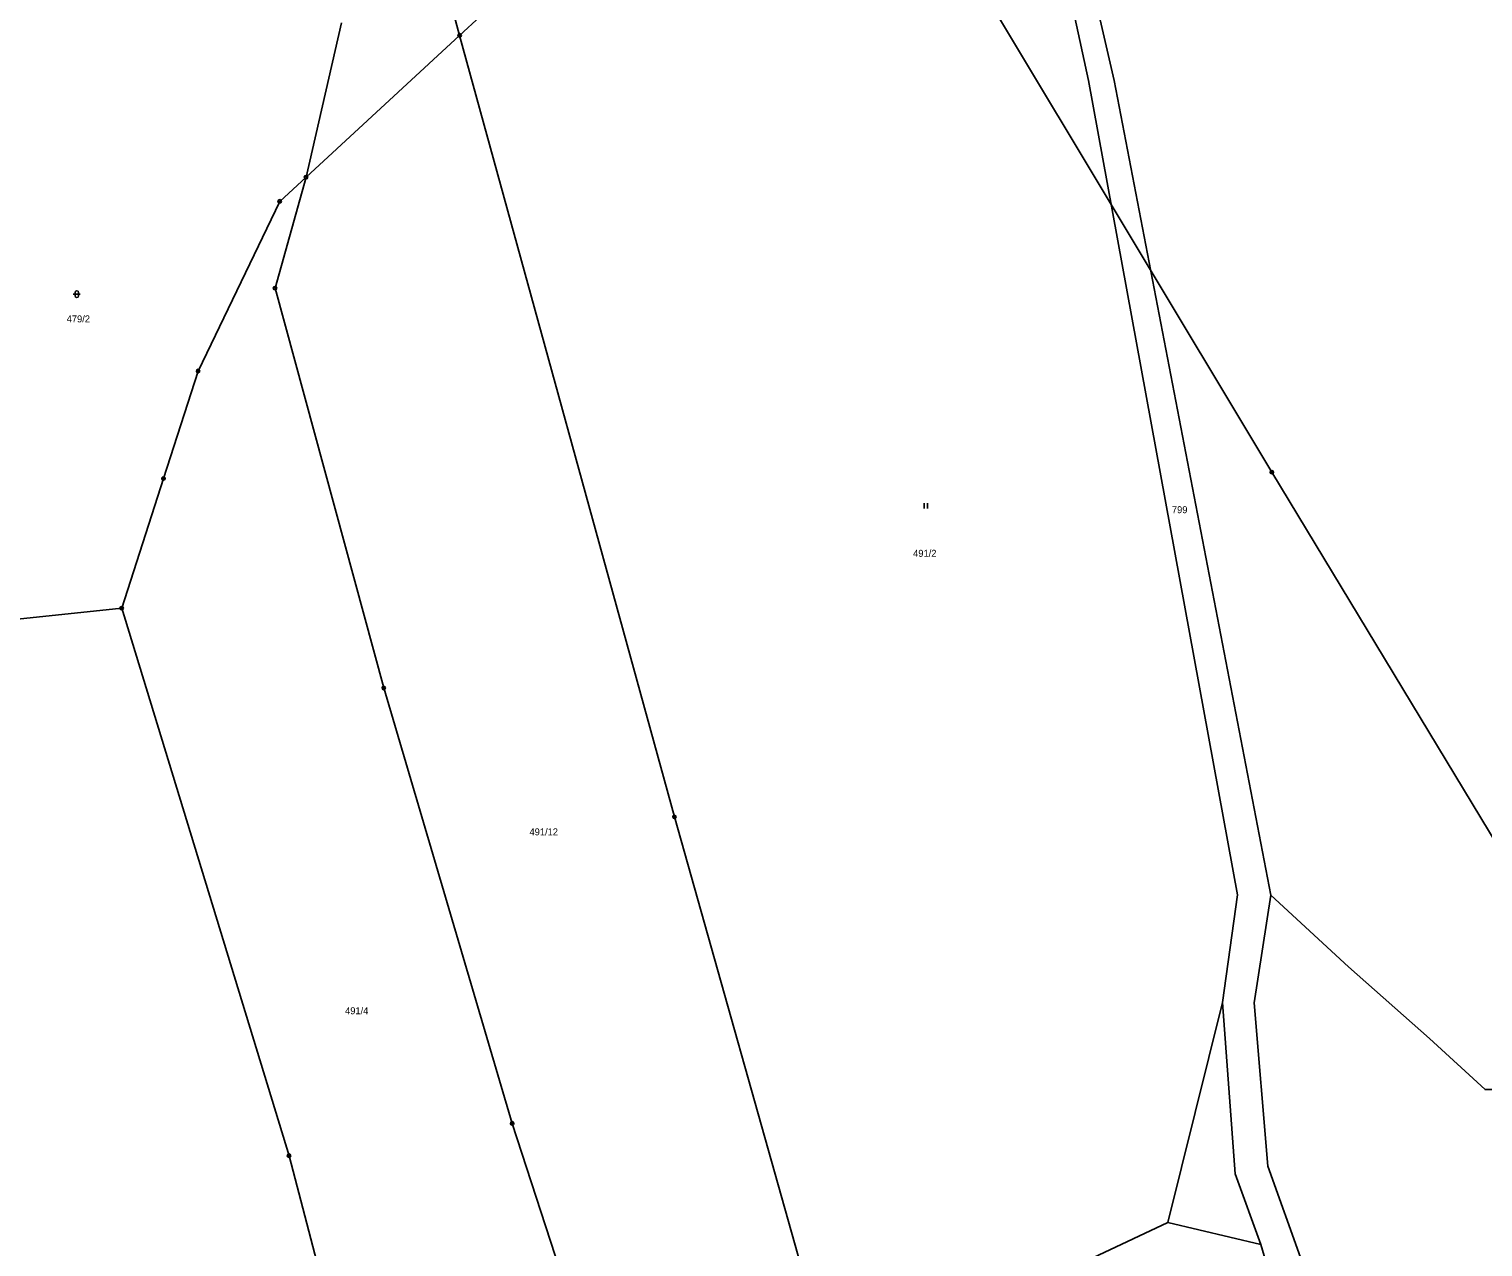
# Model space of a CAD drawing. Extents: x -745926 to -742978, y -968282 to -965689.
# Drawn here: x -744838.5 to -744629.7, y -966321.6 to -966146.7 of the extents above; entities that cross this region are included whole.
import ezdxf

# ---------------------------------------------------------------- set-up
doc = ezdxf.new("R2010")
doc.units = 0
for name, color, linetype in [('Hranice parcel', 7, 'Continuous'), ('Parcelní čísla', 7, 'Continuous'), ('Poz předměty', 7, 'Continuous'), ('Vnitřní kresba', 7, 'Continuous'), ('Značky bodu BP', 7, 'Continuous'), ('Značky kultur', 7, 'Continuous')]:
    doc.layers.add(name, color=color, linetype=linetype)

msp = doc.modelspace()

# ---------------------------------------------------------------- linework, layer by layer
at = {"layer": 'Hranice parcel'}
for p, q in [((-744776.62, -966147.65), (-744767, -966138.77)), ((-744778.24, -966141.75), (-744776.62, -966147.65)), ((-744798.68, -966168), (-744793.61, -966145.84)), ((-744776.62, -966147.65), (-744745.78, -966259.84)), ((-744745.78, -966259.84), (-744722.98, -966340.71)), ((-744659.44, -966328.45), (-744661.57, -966321.24))]:
    msp.add_line(p, q, dxfattribs=at)
for points in [[(-744661.57, -966321.24), (-744665.28, -966311.06), (-744667.08, -966286.48), (-744664.93, -966271.05), (-744686.3, -966154.12), (-744696.48, -966107.26), (-744701.19, -966088.11)], [(-744693.44, -966107.19), (-744682.62, -966154.14), (-744660.13, -966271.07)], [(-744825.15, -966229.87), (-744819.14, -966211.25), (-744814.18, -966195.83), (-744802.46, -966171.48), (-744798.68, -966168)], [(-744752.55, -966354.51), (-744769.07, -966303.83), (-744787.52, -966241.33), (-744803.13, -966183.94), (-744798.68, -966168)], [(-744499.8, -966191.27), (-744519.07, -966204.62), (-744539.66, -966223), (-744558.25, -966243.64), (-744577.47, -966262.19), (-744591.92, -966271.16), (-744607.06, -966290.29), (-744617.67, -966298.97), (-744629.36, -966298.99), (-744637.33, -966291.67), (-744648.97, -966281.37), (-744660.13, -966271.07)], [(-744825.15, -966229.87), (-744841.01, -966231.55), (-744850.95, -966217.5), (-744861.1, -966210.46), (-744873.1, -966209.43), (-744887.76, -966217.01), (-744914.42, -966230.27), (-744943.81, -966244.14), (-744968.2, -966255.83), (-745004.86, -966268.89), (-745028.4, -966275.8), (-745059.51, -966279.73), (-745085.89, -966289.8)], [(-744785, -966370.1), (-744801.12, -966308.48), (-744825.15, -966229.87)], [(-744660.13, -966271.07), (-744662.52, -966286.51), (-744660.55, -966309.96), (-744655.66, -966323.75), (-744643.75, -966362.14), (-744642.18, -966368.78), (-744642.37, -966373.98)], [(-744661.57, -966321.24), (-744674.92, -966318.05), (-744722.98, -966340.71)]]:
    msp.add_lwpolyline(points, dxfattribs=at)
at = {"layer": 'Poz předměty'}
for p, q in [((-744713.36, -966121.42), (-744659.99, -966210.34)), ((-744659.99, -966210.34), (-744619.97, -966276.55))]:
    msp.add_line(p, q, dxfattribs=at)
for radius in [0.25, 0.2, 0.15, 0.1, 0.05]:
    msp.add_circle((-744659.99, -966210.34), radius, dxfattribs=at)
at = {"layer": 'Vnitřní kresba'}
for p, q in [((-744798.68, -966168), (-744776.62, -966147.65)), ((-744674.92, -966318.05), (-744667.08, -966286.48))]:
    msp.add_line(p, q, dxfattribs=at)
at = {"layer": 'Značky bodu BP'}
for centre, radius in [((-744776.62, -966147.65), 0.25), ((-744776.62, -966147.65), 0.0152), ((-744798.68, -966168), 0.25), ((-744798.68, -966168), 0.0152), ((-744802.46, -966171.48), 0.25), ((-744802.46, -966171.48), 0.0152), ((-744803.13, -966183.94), 0.25), ((-744803.13, -966183.94), 0.0152), ((-744814.18, -966195.83), 0.25), ((-744814.18, -966195.83), 0.0152), ((-744819.14, -966211.25), 0.25), ((-744819.14, -966211.25), 0.0152), ((-744825.15, -966229.87), 0.25), ((-744825.15, -966229.87), 0.0152), ((-744787.52, -966241.33), 0.25), ((-744787.52, -966241.33), 0.0152), ((-744745.78, -966259.84), 0.25), ((-744745.78, -966259.84), 0.0152), ((-744769.07, -966303.83), 0.25), ((-744769.07, -966303.83), 0.0152), ((-744801.12, -966308.48), 0.25), ((-744801.12, -966308.48), 0.0152)]:
    msp.add_circle(centre, radius, dxfattribs=at)
at = {"layer": 'Značky kultur'}
for p, q in [((-744832.1, -966184.8), (-744831.1, -966184.8)), ((-744831.85, -966184.55), (-744831.85, -966185.05)), ((-744831.35, -966185.05), (-744831.35, -966184.55)), ((-744709.93, -966215.57), (-744709.93, -966214.82)), ((-744709.93, -966215.57), (-744709.93, -966214.82)), ((-744709.43, -966215.57), (-744709.43, -966214.82)), ((-744709.43, -966215.57), (-744709.43, -966214.82))]:
    msp.add_line(p, q, dxfattribs=at)
for centre, start, end in [((-744831.6, -966184.55), 0, 180), ((-744831.6, -966185.05), 180, 359.9879)]:
    msp.add_arc(centre, 0.25, start, end, dxfattribs=at)

# ---------------------------------------------------------------- texts
at = {"layer": 'Parcelní čísla'}
for s, p in [('479/2', (-744833.05, -966188.85)), ('799', (-744674.34, -966216.24)), ('491/2', (-744711.5, -966222.5)), ('491/12', (-744766.59, -966262.49)), ('491/4', (-744793.07, -966288.17))]:
    msp.add_text(s, height=1, dxfattribs=at).set_placement(p)

doc.saveas('drawing.dxf')
